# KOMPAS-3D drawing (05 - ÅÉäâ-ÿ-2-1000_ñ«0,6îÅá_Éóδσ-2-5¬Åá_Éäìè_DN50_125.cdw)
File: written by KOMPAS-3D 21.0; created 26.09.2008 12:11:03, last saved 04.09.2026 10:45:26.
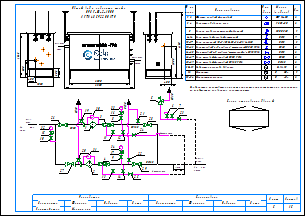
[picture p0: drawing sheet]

Sheets 1-2: A3, landscape

Document properties: Наименование: Макро:21; Автор: RaskoAdmin; Форматы листов документа: 2xA3; Полное имя файла: \\UR38nt01\Departments\КТО\КБ ПУРДГ\Заявки\Прайс-лист на типовые шкафы ГРПШ\ПРДГ_стандарт_20_03_2026\ПРДГ с РДНК\ПРДГ-Ш-2-1000_до0,6МПа_Рвых-2-5кПа_РДНК_DN50_125.cdw

Title block, sheet 1: Наименование: Пункт учета газа / ПУГ-Ш-400-Р / ЛГТИ.485922.001ТУ; designation: ЛГТИ.03.4411141; sheet number: 1; Количество листов документа: 2; organisation: ООО "ЭЛЬСТЕР Газэлектроника"; Форматы листов документа: A3; stored path: C:\Рабочие документы\Компас\ПУГ\Схема.cdw; Разработал: Устинов; Проверил: Кошкин; Утвердил: Кошкин
Title block, sheet 2: sheet number: 2; stored path: D:\Рабочие документы\Заявки\ПУРДГ\ПУРДГ-ШУЭО-2-100-Р 4411220.cdw; designation, second copy: ЛГТИ.03.4411141-

Views: Вид 1, Вид 2
Referenced files: wcvoit.frw
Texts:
  Normal
  Вход
  газа
  PDI
  Выход
  Р=     кПа
  DN125
  DN50
  DN20
  Импульс DN15
  ≥5DN
  HYSWLongFangSong
  № на
  схеме
  Усл.
  обозн.
  Марка
  (модель)
  Кол.
  Фильтр газовый фланцевый
  ФГ 16-50
  Регулятор давления газа
  РДНК-50
  Клапан предохранительный сбросной
  КПС DN20
  Кран шаровой газовый латунный
  DN15
  Кран кнопочный VE-РАСКО-НЗ-1,6-G1/2-М20
  Кран шаровой "под приварку" штуцерный DN20 PN16
  Кран шаровой "под приварку" штуцерный п/п DN15 PN16
  Кран шаровой фланцевый DN50 PN16
  Кран шаровой фланцевый DN125 PN16
  Индикатор перепада давления
  Delta 15
  Манометр
  Манометр-напоромер
  0...     МПа
  0...     кПа
  Общий вид и габариты шкафа
  ПРДГ-Ш-2-1000
  Выход газа
  Вход газа
  Схема открывания дверей
  logo-rasko-ge.png
  Предприятие изготовитель может заменять комплектующие на аналогичные,
  не ухудшающие заявленных характеристик.
  Р=        МПа
  Должность
  Конструктор
  Фамилия
  Подпись
  Дата
  Согласовано
  Максимкин
  Лист
  Листов
  POLYLINE_STYLE_0.18_RGB_0_0_0
  POLYLINE_STYLE_0.50_RGB_0_0_0
  POLYLINE_STYLE_0.34_RGB_0_0_0
  PHANTOM_RGB_0_0_0_SC_1_THICK_0.18
  K5LT_THIN_RGB_0_0_0_THICK_0.18
  K5LT32769_RGB_0_0_0_THICK_0.18
  K5LT12_RGB_0_0_0_SC_1_THICK_0.18
  K5LT_DASHED_RGB_0_0_0_SC_1_THICK_0.18
  ACISOTGL_RGB_0_0_0_SC_0.8_THICK_0.25
  CONTINUOUS_RGB_0_127_31_THICK_0.3
  CONTINUOUS_RGB_0_0_255_THICK_0.35
  CONTINUOUS_RGB_255_0_0_THICK_0.35
  POLYLINE_STYLE_0.25_RGB_0_0_0
  CONTINUOUS_RGB_0_0_0_THICK_0.5
  POLYLINE_STYLE_0.35_RGB_0_0_255
  CONTINUOUS_RGB_0_0_0_THICK_0.4
  CONTINUOUS_RGB_0_0_0_THICK_0.35
  Без оформления
Dimensions and other numbers on the sheet: 1; 2; 3; 4; 5; 10; 27; 28; 29; 23; 8; 12; 19; 20; 21; 22; 25; 24; 30; 31; 15; 16; 26; 6; 7; 11; 14; 13; 33; 1, 2; 3, 4; 6-14; 9; 15-17; 18-23; 24-25; 26-27; 28-29; 30-31; 32; 33-34; 400; 1050; 500; 305; 2500; 1565; 2800; 17; 34; 1000; 4130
